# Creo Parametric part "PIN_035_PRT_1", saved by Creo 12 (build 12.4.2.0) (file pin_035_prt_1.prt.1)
Units: Custom; MM, KILOGRAM, SECS

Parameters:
  PTC_WM_ITERATION = "0"
  PTC_WM_VERSION = "-.0"
  PTC_WM_LIFECYCLE_STATE = "In Work"
  PTC_WM_LIFECYCLE = "MO_CADDocument"
  PTC_WM_CREATED_BY = "Maximilian Roepper (Z0017RMS: MO)"
  PTC_WM_CREATED_ON = "18-Sep-26 11:36:42 AM"
  PTC_WM_MODIFIED_BY = "Maximilian Roepper (Z0017RMS: MO)"
  PTC_WM_MODIFIED_ON = "18-Sep-26 11:36:46 AM"
  PDMLINKNUMBER = "PDM000071455345"
  PTC_WM_NAME = "pin_035_prt_1.prt"
  PTC_WM_NUMBER = "PDM000071455345"

Other parameters: WEIGHT, WEIGHT_FACTOR, WEIGHT_ADD, _MASS_TEMP, _DIFF_TEMP, MC_ERRORS, SUPPLIER

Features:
  1. coordinate system
  2. datum plane "PRT_YZ"
  3. datum plane "PRT_XY"
  4. datum plane "PRT_XZ"
  5. coordinate system
  6. datum axis
  7. datum axis
  8. datum axis
  9. coordinate system
  10. imported feature
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
Other named items: PRT, SIEMENS_MO, DRW_VIEW_ORG, PRT_X, PRT_Y, PRT_Z, CS0, ROUGH_GROB

Layers: 00_STD_CSYS-KSYS, 01_STD_PLANES-EBENEN, 02_STD_AXES-ACHSEN, 03_STD_CSYS-KSYS, 24_IMPORT_FEAT-IMPORT_KE

Surfaces: 9 plane, 1 cylinder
